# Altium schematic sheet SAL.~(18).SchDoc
size A3; Date: 24-04-2009; DrawnBy: Hugo Emanuel Fonseca Tavares; PageSetup: Record=PageOptions|CenterHorizontal=True|CenterVertical=True|PrintScale=1.00|XCorrection=1.00|YCorrection=1.00|PrintKind=0|BorderSize=5000000|LeftOffset=0|BottomOffset=0|Orientation=2|PaperLength=1000|PaperWidth=1000|Scale=100|PaperSource=7|PrintQuality=-4|MediaType=1|DitherType=10|PaperKind=A3|PrintScaleMode=0
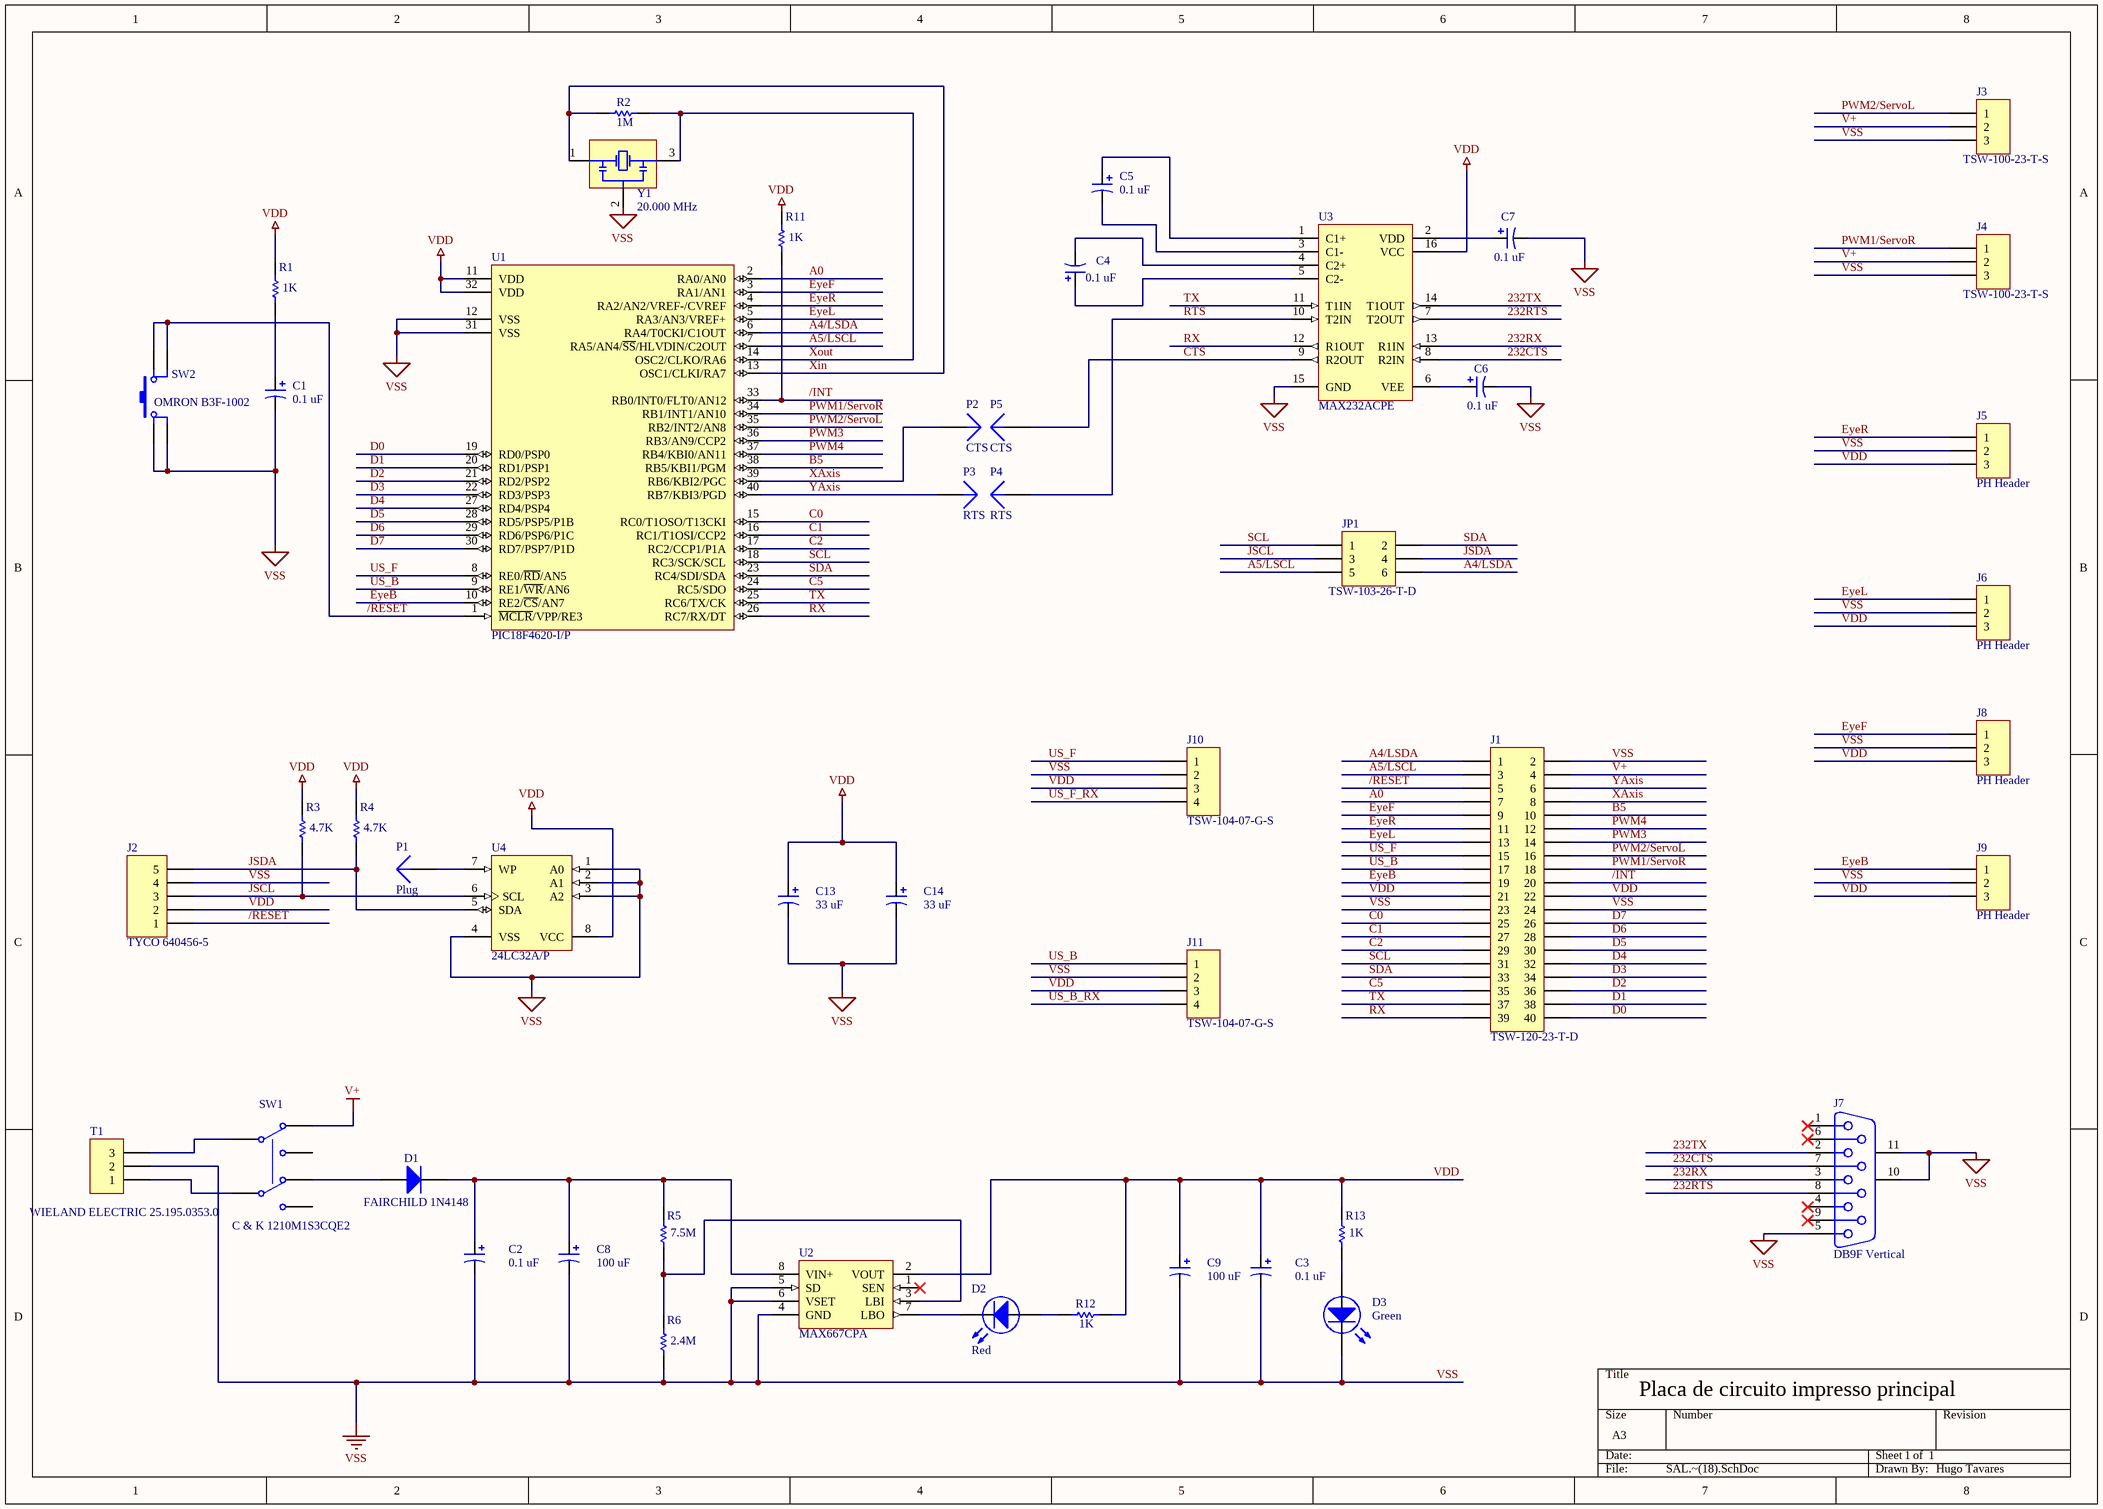
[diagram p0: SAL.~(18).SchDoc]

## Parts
C1  0.1 uF  [KEMET C410C104M5U5CA-TR]
C2  0.1 uF  [KEMET C410C104M5U5CA-TR]
C3  0.1 uF  [KEMET C410C104M5U5CA-TR]
C4  0.1 uF  [KEMET C410C104M5U5CA-TR]
C5  0.1 uF  [KEMET C410C104M5U5CA-TR]
C6  0.1 uF  [KEMET C410C104M5U5CA-TR]
C7  0.1 uF  [KEMET C410C104M5U5CA-TR]
C8  100 uF  [PANASONIC ECA1CAK101X]
C9  100 uF  [PANASONIC ECA1CAK101X]
C13  33 uF  [PANASONIC ECEA0JKS330]
C14  33 uF  [PANASONIC ECEA0JKS330]
D1  FAIRCHILD 1N4148  [FAIRCHILD 1N4118]
D2  Red  [VISHAY TLLR4401]
D3  Green  [VISHAY TLLR4401]
J1  TSW-120-23-T-D  [SAMTEC TSW-120-XX-X-D]
J2  TYCO 640456-5  [TYCO 640456-5]
J3  TSW-100-23-T-S  [SAMTEC TSW-103-XX-X-S]
J4  TSW-100-23-T-S  [SAMTEC TSW-103-XX-X-S]
J5  PH Header  [JST B3B-PH-K-S(LF)(SN)]
J6  PH Header  [JST B3B-PH-K-S(LF)(SN)]
J7  DB9F Vertical  [TYCO 1-338313-2]
J8  PH Header  [JST B3B-PH-K-S(LF)(SN)]
J9  PH Header  [JST B3B-PH-K-S(LF)(SN)]
J10  TSW-104-07-G-S  [SAMTEC TSW-104-XX-X-S]
J11  TSW-104-07-G-S  [SAMTEC TSW-104-XX-X-S]
JP1  TSW-103-26-T-D  [SAMTEC-103-XX-X-D]
P1  Plug  [PIN1]
P2  CTS  [PIN1]
P3  RTS  [PIN1]
P4  RTS  [PIN1]
P5  CTS  [PIN1]
R1  1K  [TYCO 1-1625875-2]
R2  1M  [MULTICOMP MCF 0.25W 56R]
R3  4.7K  [MULTICOMP MF12 4K7]
R4  4.7K  [MULTICOMP MF12 4K7]
R5  7.5M  [VISHAY MRS25 2M4]
R6  2.4M  [VISHAY MRS25 2M4]
R11  1K  [TYCO 1-1625875-2]
R12  1K  [TYCO 1-1625875-2]
R13  1K  [TYCO 1-1625875-2]
SW1  C & K 1210M1S3CQE2  [C & K 1201M1S3CQE2]
SW2  OMRON B3F-1002  [OMRON B3F-1002]
T1  WIELAND ELECTRIC 25.195.0353.0  [WIELAND ELECTRIC 25.195.0353.0]
U1  PIC18F4620-I/P  [PDIP600-P40]
U2  MAX667CPA  [JA8]
U3  MAX232ACPE  [PE16A]
U4  24LC32A/P  [PDIP300-P8]
Y1  20.000 MHz  [AEL CRYSTALS C20M000000L01]

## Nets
V+: J1.4 J3.2 J4.2 SW1.1(NC1)
VDD: C3.2 C9.2 C13.2 C14.2 J1.21 J1.22 J2.2 J5.3 J6.3 J8.3 J9.3 J10.3 J11.3 R1.2 R3.2 R4.2 R11.2 R12.1 R13.2 U1.11(VDD) U1.32(VDD) U2.2(VOUT) U3.16(VCC) U4.8(VCC)
VSS: C1.2 C2.1 C3.1 C6.1 C7.1 C8.1 C9.1 C13.1 C14.1 D3.1(K) J1.2 J1.23 J1.24 J2.4 J3.3 J4.3 J5.2 J6.2 J7.5 J7.10(MH1) J7.11(MH2) J8.2 J9.2 J10.2 J11.2 R6.1 SW2.3 SW2.4 T1.2 U1.12(VSS) U1.31(VSS) U2.4(GND) U2.5(SD) U2.6(VSET) U3.15(GND) U4.1(A0) U4.2(A1) U4.3(A2) U4.4(VSS) Y1.2
232CTS: J7.7 U3.8(R2IN)
232RTS: J7.8 U3.7(T2OUT)
232RX: J7.3 U3.13(R1IN)
232TX: J7.2 U3.14(T1OUT)
/INT: J1.20 R11.1 U1.33(RB0/INT0/FLT0/AN12)
/RESET: J1.5 J2.1 SW2.1 SW2.2 U1.1(~{MCLR}/VPP/RE3)
A0: J1.7 U1.2(RA0/AN0)
A4/LSDA: J1.1 JP1.6 U1.6(RA4/T0CKI/C1OUT)
A5/LSCL: J1.3 JP1.5 U1.7(RA5/AN4/~{SS}/HLVDIN/C2OUT)
B5: J1.10 U1.38(RB5/KBI1/PGM)
C0: J1.25 U1.15(RC0/T1OSO/T13CKI)
C1: J1.27 U1.16(RC1/T1OSI/CCP2)
C2: J1.29 U1.17(RC2/CCP1/P1A)
C5: J1.35 U1.24(RC5/SDO)
CTS: P5.1 U3.9(R2OUT)
D0: J1.40 U1.19(RD0/PSP0)
D1: J1.38 U1.20(RD1/PSP1)
D2: J1.36 U1.21(RD2/PSP2)
D3: J1.34 U1.22(RD3/PSP3)
D4: J1.32 U1.27(RD4/PSP4)
D5: J1.30 U1.28(RD5/PSP5/P1B)
D6: J1.28 U1.29(RD6/PSP6/P1C)
D7: J1.26 U1.30(RD7/PSP7/P1D)
EyeB: J1.19 J9.1 U1.10(RE2/~{CS}/AN7)
EyeF: J1.9 J8.1 U1.3(RA1/AN1)
EyeL: J1.13 J6.1 U1.5(RA3/AN3/VREF+)
EyeR: J1.11 J5.1 U1.4(RA2/AN2/VREF-/CVREF)
JSCL: J2.3 JP1.3 R3.1 U4.6(SCL)
JSDA: J2.5 JP1.4 R4.1 U4.5(SDA)
PWM1/ServoR: J1.18 J4.1 U1.34(RB1/INT1/AN10)
PWM2/ServoL: J1.16 J3.1 U1.35(RB2/INT2/AN8)
PWM3: J1.14 U1.36(RB3/AN9/CCP2)
PWM4: J1.12 U1.37(RB4/KBI0/AN11)
RTS: P4.1 U3.10(T2IN)
RX: J1.39 U1.26(RC7/RX/DT) U3.12(R1OUT)
SCL: J1.31 JP1.1 U1.18(RC3/SCK/SCL)
SDA: J1.33 JP1.2 U1.23(RC4/SDI/SDA)
TX: J1.37 U1.25(RC6/TX/CK) U3.11(T1IN)
US_B: J1.17 J11.1 U1.9(RE1/~{WR}/AN6)
US_B_RX: J11.4
US_F: J1.15 J10.1 U1.8(RE0/~{RD}/AN5)
US_F_RX: J10.4
XAxis: J1.8 P2.1 U1.39(RB6/KBI2/PGC)
Xin: R2.1 U1.13(OSC1/CLKI/RA7) Y1.1(OSC1)
Xout: R2.2 U1.14(OSC2/CLKO/RA6) Y1.3(OSC2)
YAxis: J1.6 P3.1 U1.40(RB7/KBI3/PGD)
NetC1_1: C1.1 R1.1
NetC2_2: C2.2 C8.2 D1.K R5.2 U2.8(VIN+)
NetC4_1: C4.1 U3.4(C2+)
NetC4_2: C4.2 U3.5(C2-)
NetC5_1: C5.1 U3.3(C1-)
NetC5_2: C5.2 U3.1(C1+)
NetC6_2: C6.2 U3.6(VEE)
NetC7_2: C7.2 U3.2(VDD)
NetD1_A: D1.A SW1.4(NC2)
NetD2_1: D2.1(A) U2.7(LBO)
NetD2_2: D2.2(K) R12.2
NetD3_2: D3.2(A) R13.1
NetP1_1: P1.1 U4.7(WP)
NetR5_1: R5.1 R6.2 U2.3(LBI)
NetSW1_2: SW1.2(COMMON1) T1.3
NetSW1_5: SW1.5(COMMON2) T1.1

Not connected (* = marked no-connect by the designer): J7 1* 4* 6* 9*; SW1 3(NO1) 6(NO2); U2 1(SEN)*

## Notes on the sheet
- Placa de circuito impresso principal
- 1      1
- Hugo Tavares

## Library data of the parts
C1-C7 = KEMET C410C104M5U5CA-TR: 0.1 uF axial capacitor 50V Z5U
C8 C9 = PANASONIC ECA1CAK101X: 100 uF radial aluminum electrolytic Capacitor 16V
C13 C14 = PANASONIC ECEA0JKS330: 33 uF radial aluminium electrolytic Capacitor 6.3V
D1 = FAIRCHILD 1N4148: Diode Switching 75V 500 MW DO-35
D2 = VISHAY TLLR4401: Red LED PCB 3mm
D3 = VISHAY TLLG4401: Green LED PCB 3mm
J1 = SAMTEC TSW-120-07-G-D: 40 pin 2.54mm pitch dual row header
J2 = TYCO 640456-5: I2C Connector
J3 J4 = SAMTEC TSW-103-07-G-S: 3 pin 2.54mm pitch header
J5 J6 J8 J9 = JST B3B-PH-K-S(LF)(SN): 2.0mm 3-pin Shrouded header
J7 = TYCO 1-338313-2: DB9 Female PCB vertical mount
J10 J11 = SAMTEC TSW-104-07-G-S: 4 pin 2.54mm pitch header
JP1 = SAMTEC TSW-103-07-G-D: 6 pin 2.54mm pitch dual row header
P2-P5 = Plug
R1 R11-R13 = TYCO 1-1625875-2: 1k Ohm 1/4 W 5%
R2 = MULTICOMP MCF 0.25W 56R: 56 Ohm 1/4 W 5%
R3 R4 = MULTICOMP MF12 4K7: 4.7k Ohm 1/4 W 5%
R5 R6 = VISHAY MRS25 7M5: 7.5M Ohm 1/4 5%
SW1 = C & K 1210M1S3CQE2: DPDT Slide Switch
SW2 = OMRON B3F-1002: 6.0mm Tact Switch
T1 = WIELAND ELECTRIC 25.195.0353.0: 3 position Terminal Block 3.5mm spacing
U1 = PIC18F4620-I/P: Enhanced Flash Microcontroller with 10-Bit A/D and nanoWatt Technology, 64K Flash, 40-Pin PDIP, Industrial Temperature Range
U2 = MAX666MJA: Dual Mode 5V/Programmable Micropower Voltage Regulator
U3 = MAX232ACPE: +5V Powered, Multi-Channel RS-232 Driver/Receiver
U4 = 24LC32A/P: 32Kbit, 400kHz, 2.5V, I2C Serial EEPROM, 8-Pin PDIP, Commercial Temperature
Y1 = AEL CRYSTALS C20M000000L01: 20.000 MHz Resoator with caps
